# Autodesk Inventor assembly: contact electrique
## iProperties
Author: BAVERGE
Created: 2002-05
Part Number: contact electrique
Document SubType Name: Assemblage
Designer: BAVERGE
Control State: 0
Master: False
Checked Out: False
PropertySet Name: Design Tracking Control
Shininess: 41.0
Angle Display Precision: 2
Document Length Units: 11269
Document Angle Units: 11283
Document Time Units: 11279
Document Mass Units: 11290
Document Length Units Precision: 3
Document Angle Units Precision: 2
Compacted: False
PropertySet Name: _Private Model Information
Density: 0.0
Volumn: 0.0
Area: 0.0
PropertySet Name: Model Information
